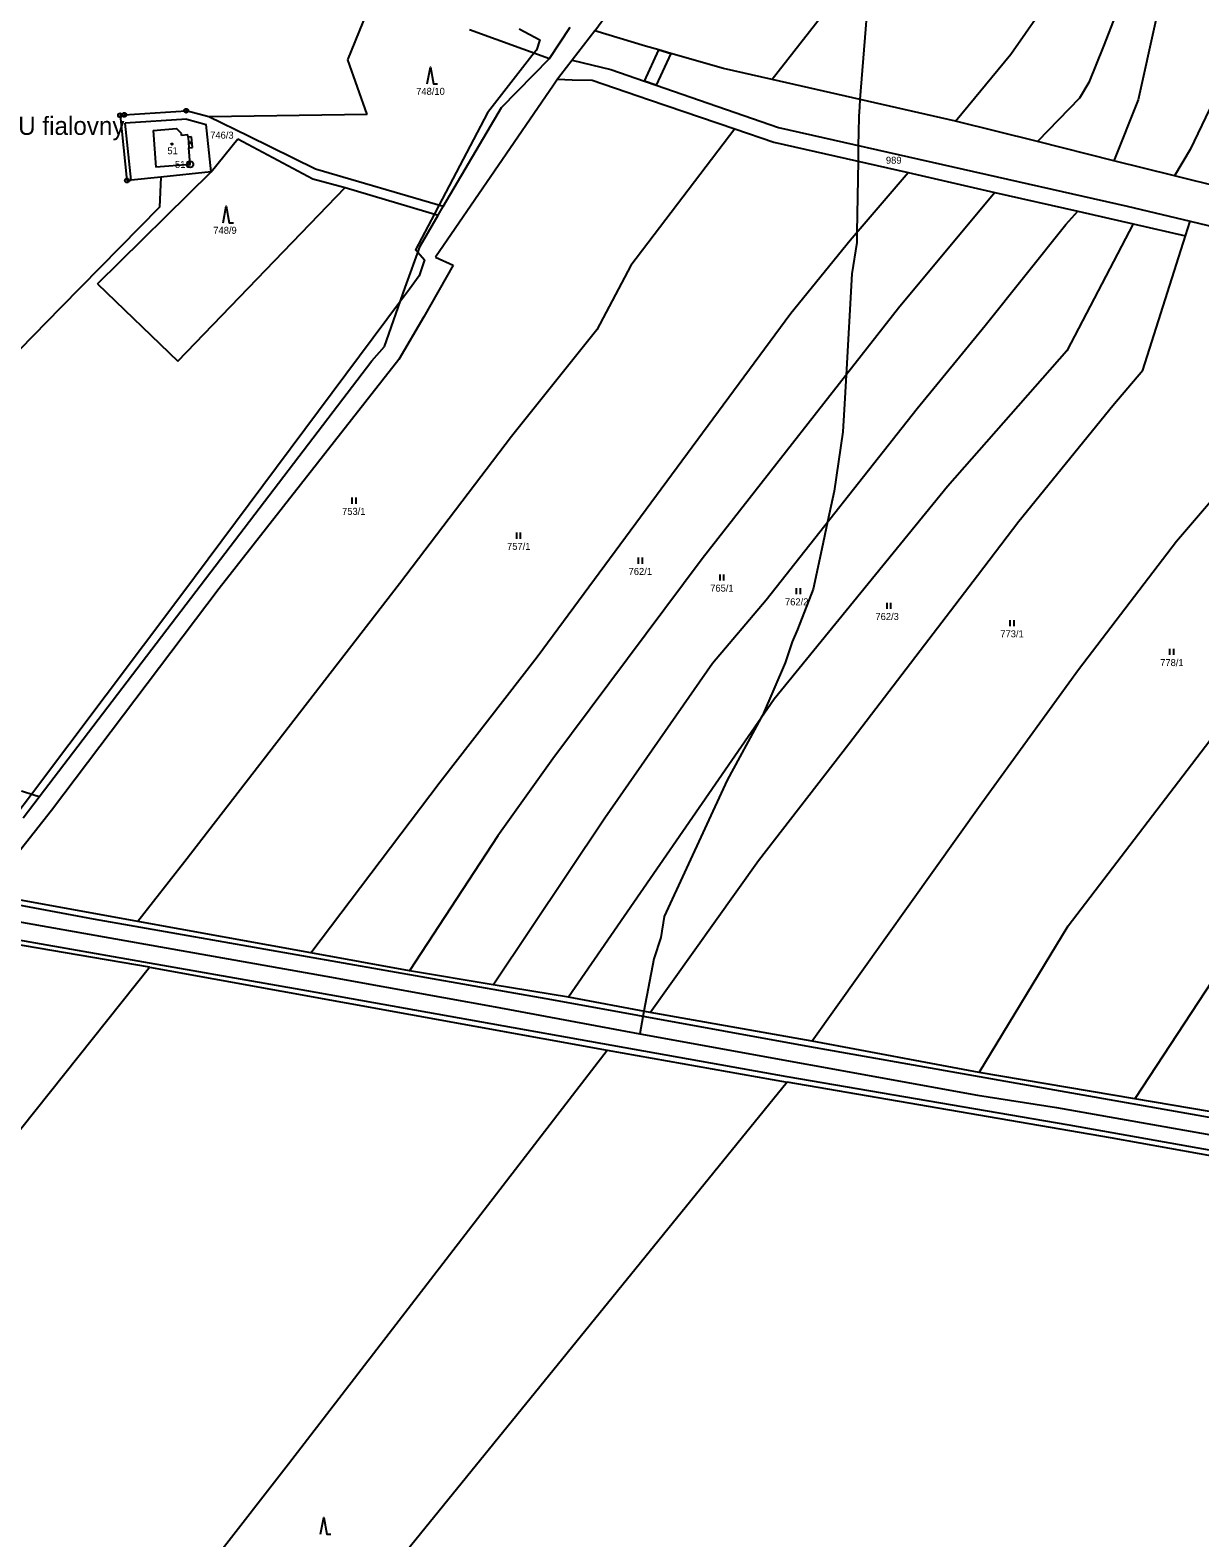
# Model space of a CAD drawing. Extents: x -749173 to -746119, y -1132678 to -1130338.
# Drawn here: x -748475.9 to -748191.7, y -1131881.8 to -1131515.5 of the extents above; entities that cross this region are included whole.
import ezdxf

# ---------------------------------------------------------------- set-up
doc = ezdxf.new("R2010")
doc.units = 0
for name, color, linetype in [('Vrstva 1', 7, 'Continuous'), ('Vrstva 15', 7, 'Continuous'), ('Vrstva 17', 7, 'Continuous'), ('Vrstva 18', 7, 'Continuous'), ('Vrstva 19', 7, 'Continuous'), ('Vrstva 24', 7, 'Continuous'), ('Vrstva 25', 7, 'Continuous'), ('Vrstva 3', 7, 'Continuous'), ('Vrstva 30', 7, 'Continuous'), ('Vrstva 37', 7, 'Continuous'), ('Vrstva 4', 7, 'Continuous'), ('Vrstva 52', 7, 'Continuous'), ('Vrstva 6', 7, 'Continuous')]:
    doc.layers.add(name, color=color, linetype=linetype)

msp = doc.modelspace()

# ---------------------------------------------------------------- linework, layer by layer
at = {"layer": 'Vrstva 1'}
for points in [[(-748338.7, -1131515.67), (-748332.06, -1131506.58)], [(-748369.17, -1131515.42), (-748349.71, -1131522.42)], [(-748349.71, -1131522.42), (-748344.69, -1131514.82)], [(-748338.7, -1131515.67), (-748344.25, -1131522.86)], [(-748326.43, -1131519.41), (-748338.7, -1131515.67)], [(-748361.37, -1131534.34), (-748349.71, -1131522.42)], [(-748323.16, -1131520.36), (-748326.43, -1131519.41)], [(-748320.25, -1131521.2), (-748323.16, -1131520.36)], [(-748307.46, -1131524.9), (-748320.25, -1131521.2)], [(-748346.96, -1131526.43), (-748347.75, -1131527.48)], [(-748344.25, -1131522.86), (-748346.96, -1131526.43)], [(-748344.25, -1131522.86), (-748334.86, -1131525.13)], [(-748334.86, -1131525.13), (-748326.65, -1131527.96)], [(-748295.63, -1131527.57), (-748307.46, -1131524.9)], [(-748348.74, -1131528.93), (-748377.39, -1131570.73)], [(-748347.75, -1131527.48), (-748348.74, -1131528.93)], [(-748347.75, -1131527.48), (-748344.25, -1131527.58)], [(-748344.25, -1131527.58), (-748339.37, -1131527.72)], [(-748339.37, -1131527.72), (-748328.27, -1131531.5)], [(-748326.65, -1131527.96), (-748323.79, -1131528.94)], [(-748323.79, -1131528.94), (-748294.08, -1131539.17)], [(-748251.1, -1131537.65), (-748295.63, -1131527.57)], [(-748328.27, -1131531.5), (-748325.41, -1131532.47)], [(-748325.41, -1131532.47), (-748304.71, -1131539.52)], [(-748454.05, -1131536.22), (-748453.04, -1131536.11)], [(-748454.05, -1131536.22), (-748452.39, -1131552.07)], [(-748453.04, -1131536.11), (-748437.99, -1131535.12)], [(-748437.84, -1131537.2), (-748452.83, -1131538.17)], [(-748432.47, -1131536.6), (-748437.99, -1131535.12)], [(-748437.84, -1131537.2), (-748433.11, -1131538.5)], [(-748422.84, -1131541.28), (-748432.47, -1131536.6)], [(-748375.6, -1131558.41), (-748361.37, -1131534.34)], [(-748451.39, -1131551.97), (-748452.83, -1131538.17)], [(-748431.92, -1131549.94), (-748433.11, -1131538.5)], [(-748304.71, -1131539.52), (-748295.27, -1131542.73)], [(-748294.08, -1131539.17), (-748209.42, -1131558.33)], [(-748231.2, -1131542.62), (-748251.1, -1131537.65)], [(-748431.92, -1131549.94), (-748425.42, -1131541.92)], [(-748425.42, -1131541.92), (-748407.25, -1131551.64)], [(-748406.59, -1131549.32), (-748422.84, -1131541.28)], [(-748295.27, -1131542.73), (-748262.6, -1131550.16)], [(-748212.64, -1131547.25), (-748231.2, -1131542.62)], [(-748197.93, -1131550.92), (-748212.64, -1131547.25)], [(-748452.39, -1131552.07), (-748451.39, -1131551.97)], [(-748444.16, -1131551.22), (-748451.39, -1131551.97)], [(-748431.92, -1131549.94), (-748444.16, -1131551.22)], [(-748407.25, -1131551.64), (-748399.33, -1131553.79)], [(-748375.6, -1131558.41), (-748406.59, -1131549.32)], [(-748262.6, -1131550.16), (-748241.52, -1131554.96)], [(-748186.16, -1131553.86), (-748197.93, -1131550.92)], [(-748399.33, -1131553.79), (-748376.75, -1131560.47)], [(-748241.52, -1131554.96), (-748221.35, -1131559.55)], [(-748376.75, -1131560.47), (-748375.6, -1131558.41)], [(-748209.42, -1131558.33), (-748194.06, -1131561.97)], [(-748381.17, -1131567.99), (-748376.75, -1131560.47)], [(-748221.35, -1131559.55), (-748207.96, -1131562.6)], [(-748207.96, -1131562.6), (-748195.25, -1131565.49)], [(-748195.25, -1131565.49), (-748194.06, -1131561.97)], [(-748194.06, -1131561.97), (-748153.68, -1131571.69)], [(-748384.76, -1131578.08), (-748381.17, -1131567.99)], [(-748373.15, -1131572.6), (-748380.27, -1131585.17)], [(-748377.39, -1131570.73), (-748373.15, -1131572.6)], [(-748389.85, -1131592.41), (-748384.76, -1131578.08)], [(-748380.27, -1131585.17), (-748386.35, -1131595.53)], [(-748392.88, -1131595.87), (-748389.85, -1131592.41)], [(-748473.73, -1131701.81), (-748392.88, -1131595.87)], [(-748386.35, -1131595.53), (-748430, -1131651.16)], [(-748430, -1131651.16), (-748470.71, -1131705.15)], [(-748475.01, -1131701.42), (-748477.99, -1131700.43)], [(-748477.57, -1131706.86), (-748473.73, -1131701.81)], [(-748473.73, -1131701.81), (-748475.01, -1131701.42)], [(-748470.71, -1131705.15), (-748486.77, -1131725.36)], [(-748449.71, -1131732.09), (-748486.77, -1131725.36)], [(-748407.72, -1131739.65), (-748449.71, -1131732.09)], [(-748446.88, -1131743.14), (-748491.15, -1131735.61)], [(-748383.77, -1131744.02), (-748407.72, -1131739.65)], [(-748530.22, -1131847.71), (-748446.88, -1131743.14)], [(-748446.88, -1131743.14), (-748335.68, -1131763.31)], [(-748363.42, -1131747.42), (-748383.77, -1131744.02)], [(-748345.13, -1131750.42), (-748363.42, -1131747.42)], [(-748325.27, -1131754.18), (-748345.13, -1131750.42)], [(-748285.94, -1131761.16), (-748325.27, -1131754.18)], [(-748413.16, -1131863.8), (-748335.68, -1131763.31)], [(-748335.68, -1131763.31), (-748292.03, -1131771.09)], [(-748245.31, -1131768.76), (-748285.94, -1131761.16)], [(-748292.03, -1131771.09), (-748393.32, -1131895.86)], [(-748213.42, -1131784.62), (-748292.03, -1131771.09)], [(-748207.51, -1131775.13), (-748245.31, -1131768.76)], [(-748189.42, -1131778.25), (-748207.51, -1131775.13)], [(-748177.37, -1131791.12), (-748213.42, -1131784.62)], [(-748483.93, -1131954.75), (-748413.16, -1131863.8)]]:
    msp.add_lwpolyline(points, dxfattribs=at)
at = {"layer": 'Vrstva 24'}
for p, q in [((-748454.1, -1131536.22), (-748454, -1131536.22)), ((-748453.09, -1131536.11), (-748452.99, -1131536.11)), ((-748438.04, -1131535.12), (-748437.94, -1131535.12)), ((-748437.06, -1131548.16), (-748436.96, -1131548.16)), ((-748452.44, -1131552.07), (-748452.34, -1131552.07))]:
    msp.add_line(p, q, dxfattribs=at)
for centre, radius in [((-748454.05, -1131536.22), 0.499), ((-748453.04, -1131536.11), 0.499), ((-748437.99, -1131535.12), 0.499), ((-748437.01, -1131548.16), 0.756), ((-748452.39, -1131552.07), 0.499)]:
    msp.add_circle(centre, radius, dxfattribs=at)
at = {"layer": 'Vrstva 25'}
for p, q in [((-748397.71, -1131629.09), (-748397.71, -1131630.59)), ((-748396.71, -1131630.59), (-748396.71, -1131629.09)), ((-748357.75, -1131637.6), (-748357.75, -1131639.1)), ((-748356.75, -1131639.1), (-748356.75, -1131637.6)), ((-748328.16, -1131643.68), (-748328.16, -1131645.18)), ((-748327.16, -1131645.18), (-748327.16, -1131643.68)), ((-748308.36, -1131647.74), (-748308.36, -1131649.24)), ((-748307.36, -1131649.24), (-748307.36, -1131647.74)), ((-748289.79, -1131651.07), (-748289.79, -1131652.57)), ((-748288.79, -1131652.57), (-748288.79, -1131651.07)), ((-748267.81, -1131654.64), (-748267.81, -1131656.14)), ((-748266.81, -1131656.14), (-748266.81, -1131654.64)), ((-748237.88, -1131658.84), (-748237.88, -1131660.34)), ((-748236.88, -1131660.34), (-748236.88, -1131658.84)), ((-748199.09, -1131665.83), (-748199.09, -1131667.33)), ((-748198.09, -1131667.33), (-748198.09, -1131665.83))]:
    msp.add_line(p, q, dxfattribs=at)
for points in [[(-748379.42, -1131528.56), (-748378.67, -1131524.56), (-748377.92, -1131528.56), (-748376.92, -1131528.56)], [(-748429.03, -1131562.32), (-748428.28, -1131558.32), (-748427.53, -1131562.32), (-748426.53, -1131562.32)], [(-748405.33, -1131880.89), (-748404.58, -1131876.89), (-748403.83, -1131880.89), (-748402.83, -1131880.89)]]:
    msp.add_lwpolyline(points, dxfattribs=at)
for centre in [(-748441.45, -1131543.23), (-748436.99, -1131542.92)]:
    msp.add_circle(centre, 0.175, dxfattribs=at)
at = {"layer": 'Vrstva 3'}
for points in [[(-748446.02, -1131539.95), (-748440.32, -1131539.47)], [(-748446.02, -1131539.95), (-748445.36, -1131548.79)], [(-748439.13, -1131540.67), (-748440.32, -1131539.47)], [(-748439.09, -1131541.12), (-748439.13, -1131540.67)], [(-748437.55, -1131541), (-748439.09, -1131541.12)], [(-748437.51, -1131541.55), (-748437.55, -1131541)], [(-748437.51, -1131541.55), (-748437.31, -1131544.13)], [(-748437.01, -1131548.16), (-748437.31, -1131544.13)], [(-748437.01, -1131548.16), (-748445.36, -1131548.79)]]:
    msp.add_lwpolyline(points, dxfattribs=at)
at = {"layer": 'Vrstva 30'}
msp.add_lwpolyline([(-748323.16, -1131520.36), (-748320.25, -1131521.2), (-748323.79, -1131528.94), (-748326.65, -1131527.96), (-748323.16, -1131520.36)], dxfattribs=at)
at = {"layer": 'Vrstva 37'}
msp.add_circle((-748441.45, -1131543.23), 0.175, dxfattribs=at)
at = {"layer": 'Vrstva 4'}
for points in [[(-748446.02, -1131539.95), (-748440.32, -1131539.47)], [(-748446.02, -1131539.95), (-748445.36, -1131548.79)], [(-748439.13, -1131540.67), (-748440.32, -1131539.47)], [(-748439.09, -1131541.12), (-748439.13, -1131540.67)], [(-748437.55, -1131541), (-748439.09, -1131541.12)], [(-748437.51, -1131541.55), (-748437.55, -1131541)], [(-748436.66, -1131541.49), (-748437.51, -1131541.55)], [(-748437.51, -1131541.55), (-748437.31, -1131544.13)], [(-748437.31, -1131544.13), (-748436.47, -1131544.07)], [(-748437.01, -1131548.16), (-748437.31, -1131544.13)], [(-748436.47, -1131544.07), (-748436.66, -1131541.49)], [(-748437.01, -1131548.16), (-748445.36, -1131548.79)], [(-748460.54, -1131731.48), (-748487.83, -1131726.39)], [(-748349.14, -1131751.08), (-748460.54, -1131731.48)], [(-748408.71, -1131748.93), (-748490.74, -1131734.47)], [(-748292.01, -1131769.8), (-748408.71, -1131748.93)], [(-748286.51, -1131762.56), (-748349.14, -1131751.08)], [(-748171.11, -1131782.91), (-748286.51, -1131762.56)], [(-748223.47, -1131781.55), (-748292.01, -1131769.8)], [(-748095.39, -1131804.42), (-748223.47, -1131781.55)]]:
    msp.add_lwpolyline(points, dxfattribs=at)
at = {"layer": 'Vrstva 52'}
for points in [[(-748101.82, -1131197.57), (-748128.75, -1131227.75), (-748156, -1131261), (-748164.94, -1131273.75), (-748191.69, -1131309.37), (-748224, -1131352.75), (-748231.25, -1131363), (-748232.94, -1131366.37), (-748237.19, -1131373.25), (-748246.12, -1131391.12), (-748246.24, -1131391.44), (-748246.42, -1131391.89), (-748259.31, -1131426.75), (-748266.56, -1131460), (-748269.56, -1131480), (-748271.25, -1131493.12), (-748271.53, -1131496.77), (-748272.98, -1131515.29), (-748274.31, -1131532.4)], [(-748357.12, -1131515.25), (-748352.06, -1131517.87), (-748352.87, -1131520.37), (-748353.43, -1131521.08), (-748364.81, -1131535.62), (-748376.61, -1131558.11), (-748377.7, -1131560.19), (-748382.25, -1131568.87), (-748381.71, -1131569.51), (-748380.12, -1131571.37), (-748381.37, -1131575.25), (-748383.76, -1131578.45), (-748385.93, -1131581.36), (-748439.25, -1131653), (-748475.57, -1131701.23), (-748479.37, -1131706.28), (-748479.62, -1131706.62), (-748483, -1131711.75), (-748492.01, -1131724.4), (-748495.37, -1131729.12), (-748404.08, -1131745.39), (-748375.44, -1131750.5), (-748362.92, -1131752.83), (-748327.81, -1131759.37)], [(-748274.31, -1131532.4), (-748274.44, -1131534.15), (-748274.62, -1131536.5), (-748274.68, -1131540.42), (-748274.73, -1131543.55), (-748274.78, -1131547.39), (-748275.03, -1131564.61), (-748275.06, -1131567.12), (-748276.31, -1131574.75), (-748277.67, -1131599.35), (-748278.14, -1131607.69), (-748278.44, -1131613.12), (-748280.56, -1131627.5), (-748282.17, -1131635), (-748283.58, -1131641.55), (-748285.69, -1131651.37), (-748289.5, -1131661.12), (-748290.81, -1131664.12), (-748292.5, -1131669.25), (-748298, -1131682), (-748298.36, -1131682.66), (-748306.56, -1131697.75), (-748321.87, -1131730.87), (-748322.69, -1131736), (-748324.37, -1131741.12), (-748326.78, -1131753.89), (-748327.81, -1131759.37)], [(-748327.81, -1131759.37), (-748245.75, -1131774.25), (-748226.56, -1131777.25), (-748099.44, -1131799.75), (-748024.12, -1131814.25), (-747981.19, -1131822.75)]]:
    msp.add_lwpolyline(points, dxfattribs=at)
at = {"layer": 'Vrstva 6'}
for points in [[(-748247.36, -1131465.87), (-748295.63, -1131527.57)], [(-748202.99, -1131488.16), (-748215.12, -1131519.4)], [(-748398.68, -1131522.74), (-748392.16, -1131506.55)], [(-748237.67, -1131521.37), (-748226.97, -1131506.03)], [(-748202.43, -1131513.11), (-748206.7, -1131532.49)], [(-748394.02, -1131536.07), (-748398.68, -1131522.74)], [(-748251.1, -1131537.65), (-748237.67, -1131521.37)], [(-748215.12, -1131519.4), (-748218.72, -1131528.27)], [(-748218.72, -1131528.27), (-748221.01, -1131532.05)], [(-748221.01, -1131532.05), (-748231.2, -1131542.62)], [(-748206.7, -1131532.49), (-748212.64, -1131547.25)], [(-748394.02, -1131536.07), (-748432.47, -1131536.6)], [(-748189.38, -1131534.76), (-748194.08, -1131544.52)], [(-748304.71, -1131539.52), (-748330.01, -1131572.7)], [(-748194.08, -1131544.52), (-748197.93, -1131550.92)], [(-748459.5, -1131577.18), (-748431.92, -1131549.94)], [(-748444.16, -1131551.22), (-748444.47, -1131558.56)], [(-748276.68, -1131566.53), (-748262.6, -1131550.16)], [(-748440.01, -1131595.93), (-748399.33, -1131553.79)], [(-748241.52, -1131554.96), (-748264.94, -1131583.09)], [(-748444.47, -1131558.56), (-748468.46, -1131582.9)], [(-748243.89, -1131587.32), (-748224.32, -1131562.77)], [(-748224.32, -1131562.77), (-748221.35, -1131559.55)], [(-748207.96, -1131562.6), (-748224.07, -1131593.46)], [(-748291.14, -1131584.32), (-748276.68, -1131566.53)], [(-748205.55, -1131598.18), (-748195.25, -1131565.49)], [(-748330.01, -1131572.7), (-748338.21, -1131588.38)], [(-748459.5, -1131577.18), (-748440.01, -1131595.93)], [(-748468.46, -1131582.9), (-748505.15, -1131620.41)], [(-748352.73, -1131667.79), (-748291.14, -1131584.32)], [(-748264.94, -1131583.09), (-748312.63, -1131643.99)], [(-748338.21, -1131588.38), (-748358.92, -1131614.29)], [(-748260.4, -1131607.42), (-748243.89, -1131587.32)], [(-748224.07, -1131593.46), (-748253.07, -1131626.4)], [(-748212.89, -1131606.75), (-748205.55, -1131598.18)], [(-748235.68, -1131634.79), (-748212.89, -1131606.75)], [(-748297.09, -1131653.9), (-748260.4, -1131607.42)], [(-748358.92, -1131614.29), (-748386.17, -1131650.03)], [(-748183.36, -1131623.35), (-748197.42, -1131639.78)], [(-748253.07, -1131626.4), (-748295.17, -1131678.04)], [(-748245.73, -1131647.99), (-748235.68, -1131634.79)], [(-748197.42, -1131639.78), (-748221.18, -1131670.97)], [(-748312.63, -1131643.99), (-748348.88, -1131692.58)], [(-748386.17, -1131650.03), (-748438.32, -1131717.49)], [(-748277, -1131688.88), (-748245.73, -1131647.99)], [(-748310.1, -1131669.29), (-748297.09, -1131653.9)], [(-748376.31, -1131698.17), (-748352.73, -1131667.79)], [(-748336.31, -1131706.87), (-748310.1, -1131669.29)], [(-748221.18, -1131670.97), (-748244.67, -1131703.3)], [(-748295.17, -1131678.04), (-748345.13, -1131750.42)], [(-748223.72, -1131733.12), (-748187.2, -1131685.33)], [(-748298.92, -1131717.28), (-748277, -1131688.88)], [(-748348.88, -1131692.58), (-748362.25, -1131711.28)], [(-748407.72, -1131739.65), (-748376.31, -1131698.17)], [(-748244.67, -1131703.3), (-748285.94, -1131761.16)], [(-748363.42, -1131747.42), (-748336.31, -1131706.87)], [(-748362.25, -1131711.28), (-748383.77, -1131744.02)], [(-748438.32, -1131717.49), (-748449.71, -1131732.09)], [(-748325.27, -1131754.18), (-748298.92, -1131717.28)], [(-748245.31, -1131768.76), (-748223.72, -1131733.12)], [(-748188.65, -1131746.41), (-748207.51, -1131775.13)]]:
    msp.add_lwpolyline(points, dxfattribs=at)

# ---------------------------------------------------------------- texts
at = {"layer": 'Vrstva 15'}
msp.add_text('U fialovny', height=4.4, dxfattribs=at).set_placement((-748478.81, -1131540.99))
at = {"layer": 'Vrstva 17'}
msp.add_text('516', height=1.7, dxfattribs=at).set_placement((-748440.71, -1131549.01))
at = {"layer": 'Vrstva 18'}
for s, p in [('748/10', (-748382.11, -1131531.26)), ('746/3', (-748432.16, -1131541.91)), ('989', (-748268, -1131548)), ('748/9', (-748431.4, -1131565.02)), ('753/1', (-748400.12, -1131633.29)), ('757/1', (-748360.04, -1131641.8)), ('762/1', (-748330.51, -1131647.88)), ('765/1', (-748310.69, -1131651.94)), ('762/2', (-748292.52, -1131655.27)), ('762/3', (-748270.55, -1131658.84)), ('773/1', (-748240.21, -1131663.04)), ('778/1', (-748201.37, -1131670.03))]:
    msp.add_text(s, height=1.7, dxfattribs=at).set_placement(p)
at = {"layer": 'Vrstva 19'}
msp.add_text('51', height=1.7, dxfattribs=at).set_placement((-748442.55, -1131545.68))

doc.saveas('drawing.dxf')
